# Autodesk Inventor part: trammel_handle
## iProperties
Created: 2008-11
Part Number: trammel_handle
Document SubType Name: Modeling
Designer: Lochan
Density: 1 g/cm^3
Author: Lochan
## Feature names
1. Extrusion1
2. Extrusion2
